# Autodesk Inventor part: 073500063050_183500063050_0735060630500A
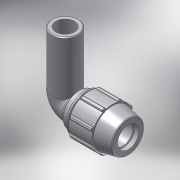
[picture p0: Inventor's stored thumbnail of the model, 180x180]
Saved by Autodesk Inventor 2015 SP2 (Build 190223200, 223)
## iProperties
Created: 2017-02
Part Number: 073500063050_183500063050_0735060630500A
Material: PVC-Piping
Description: PLASSON 90° ELBOW ADAPTOR 63-50
Document SubType Name: Modeling
Designer: KIM
Mass: 92.6774 g
Surface Area: 199.44 cm^2
Volume: 66.1981 cm^3
Density: 1.4 g/cm^3
Appearance: Smooth - White
Author: KIM
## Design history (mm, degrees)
derived "07350.ipt"
feature "Solid1::07350.ipt"
tag "TaggingFeature1"
body "Solid1"
other parameters: "d2" = 63, "d4" = 13.41667, "d5" = 40.25, "d7" = 113, "d11" = 5.36667, "d13" = 120 deg, "d14" = 81.9, "d15" = 12 deg, "d16" = 98.31, "d18" = 3.15, "d19" = 35 deg, "d20" = 17.5 deg, "d21" = 105.09, "d23" = 0, "d25" = 360 deg, "d27" = 2.26, "d33" = 1.26, "d42" = 59.57, "d43" = 3.39, "d46" = 1.89, "d51" = 161, "d68" = 5.36667, "d76" = 35, "d80" = 1.5, "d91" = 84.75, "d95" = 35, "d96" = 13.41667, "d97" = 50 deg, "d98" = 72, "d99" = 0, "d100" = 0, "d_" = 63, "E_" = 113, "A_" = 161
